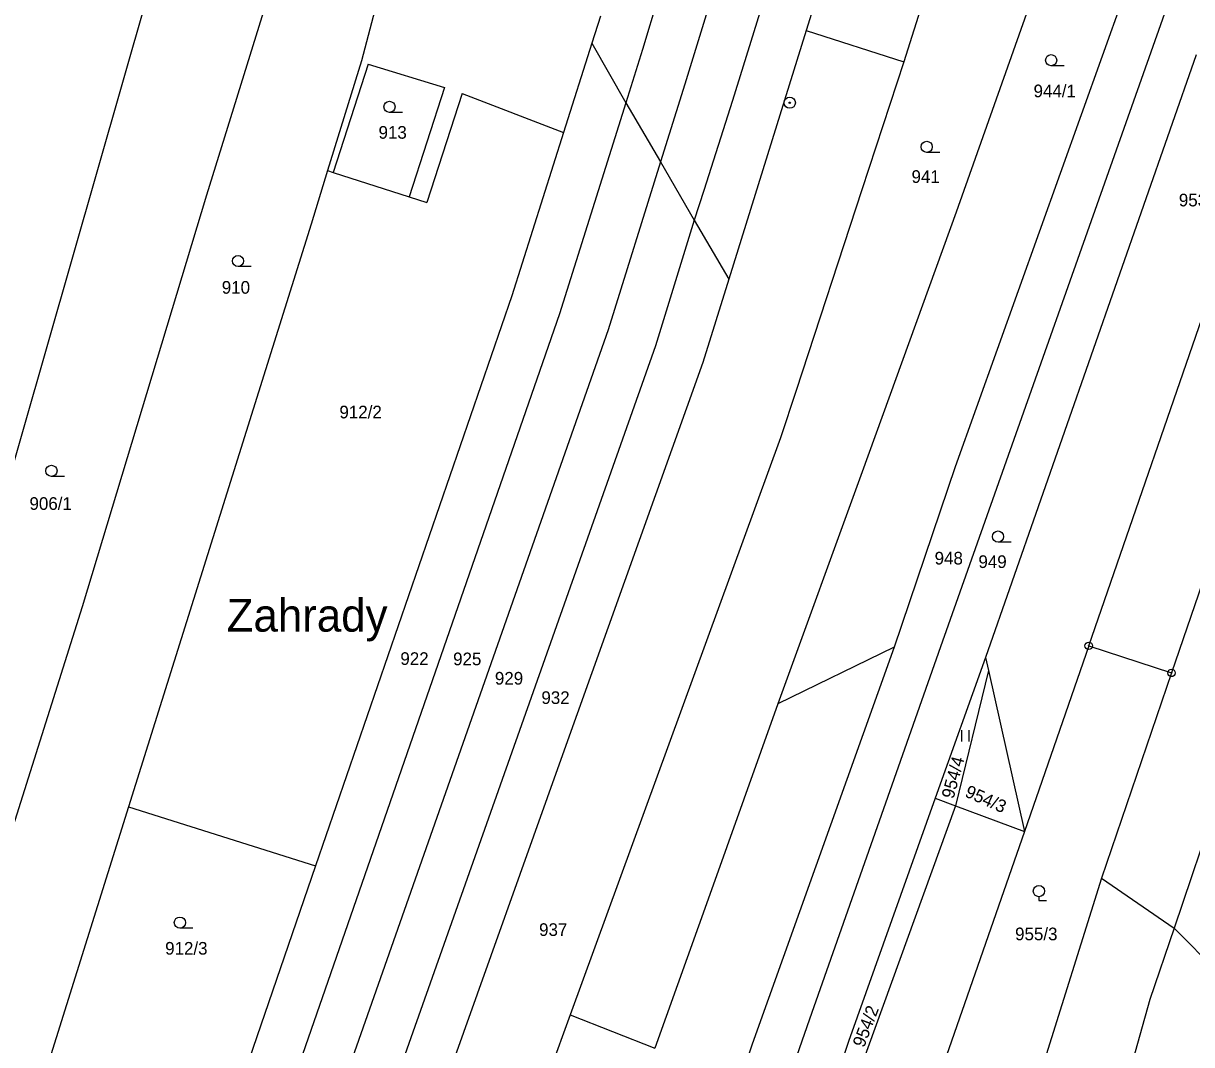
# Model space of a CAD drawing. Extents: x -593183 to -588034, y -1130415 to -1124994.
# Drawn here: x -591498.3 to -591341.4, y -1129053.4 to -1128916.3 of the extents above; entities that cross this region are included whole.
import ezdxf

# ---------------------------------------------------------------- set-up
doc = ezdxf.new("R2010")
doc.units = 0
for name, color, linetype in [('Vrstva 1', 7, 'Continuous'), ('Vrstva 15', 7, 'Continuous'), ('Vrstva 18', 7, 'Continuous'), ('Vrstva 24', 7, 'Continuous'), ('Vrstva 25', 7, 'Continuous')]:
    doc.layers.add(name, color=color, linetype=linetype)

msp = doc.modelspace()

# ---------------------------------------------------------------- linework, layer by layer
at = {"layer": 'Vrstva 1'}
for p, q in [((-591354.26, -1128888.5), (-591373.06, -1128941.67)), ((-591475.46, -1128891.06), (-591504.12, -1128991.17)), ((-591385.67, -1128893.19), (-591393.19, -1128917.3)), ((-591372.62, -1128898.03), (-591380.08, -1128921.49)), ((-591339.33, -1128898.75), (-591375.16, -1128999.99)), ((-591409.64, -1128901.35), (-591415.13, -1128919.86)), ((-591402.86, -1128903.1), (-591409.49, -1128924.51)), ((-591347.4, -1128903.87), (-591373.19, -1128975.86)), ((-591463.22, -1128905.61), (-591473.69, -1128939.41)), ((-591396.41, -1128905.12), (-591403.07, -1128926.71)), ((-591449.72, -1128909.27), (-591452.86, -1128921.36)), ((-591355.26, -1128999.87), (-591324.51, -1128910.84)), ((-591313.09, -1128912.48), (-591344.14, -1129003.51)), ((-591420.79, -1128915.38), (-591421.94, -1128918.99)), ((-591393.19, -1128917.3), (-591403.55, -1128950.65)), ((-591393.19, -1128917.3), (-591380.08, -1128921.49)), ((-591421.94, -1128918.99), (-591425.74, -1128930.99)), ((-591421.94, -1128918.99), (-591417.38, -1128927)), ((-591415.13, -1128919.86), (-591417.38, -1128927)), ((-591452.86, -1128921.36), (-591457.42, -1128936.09)), ((-591340.85, -1128920.55), (-591369.1, -1129001.43)), ((-591451.99, -1128921.8), (-591456.65, -1128936.34)), ((-591451.99, -1128921.8), (-591441.72, -1128924.93)), ((-591380.08, -1128921.49), (-591385.69, -1128938.68)), ((-591409.49, -1128924.51), (-591412.75, -1128934.94)), ((-591441.72, -1128924.93), (-591446.46, -1128939.61)), ((-591439.36, -1128925.74), (-591444.08, -1128940.37)), ((-591439.36, -1128925.74), (-591425.74, -1128930.99)), ((-591417.38, -1128927), (-591426.29, -1128955.33)), ((-591417.38, -1128927), (-591412.75, -1128934.94)), ((-591403.07, -1128926.71), (-591406.92, -1128938.75)), ((-591425.74, -1128930.99), (-591432.7, -1128952.91)), ((-591412.75, -1128934.94), (-591419.75, -1128957.47)), ((-591412.75, -1128934.94), (-591408.2, -1128942.74)), ((-591457.42, -1128936.09), (-591459.64, -1128943.27)), ((-591457.42, -1128936.09), (-591456.65, -1128936.34)), ((-591456.65, -1128936.34), (-591446.46, -1128939.61)), ((-591385.69, -1128938.68), (-591394.53, -1128965.59)), ((-591473.69, -1128939.41), (-591490.35, -1128994.63)), ((-591446.46, -1128939.61), (-591444.08, -1128940.37)), ((-591406.92, -1128938.75), (-591408.2, -1128942.74)), ((-591373.06, -1128941.67), (-591385.68, -1128976.53)), ((-591459.64, -1128943.27), (-591484.16, -1129021.5)), ((-591408.2, -1128942.74), (-591413.4, -1128959.6)), ((-591408.2, -1128942.74), (-591403.55, -1128950.65)), ((-591403.55, -1128950.65), (-591407.04, -1128961.87)), ((-591432.7, -1128952.91), (-591459.03, -1129029.38)), ((-591426.29, -1128955.33), (-591466.83, -1129072.14)), ((-591419.75, -1128957.47), (-591460.61, -1129073.72)), ((-591413.4, -1128959.6), (-591454.3, -1129075.24)), ((-591407.04, -1128961.87), (-591426.12, -1129015.15)), ((-591394.53, -1128965.59), (-591396.63, -1128971.97)), ((-591396.63, -1128971.97), (-591424.87, -1129049.39)), ((-591373.19, -1128975.86), (-591381.38, -1129000.06)), ((-591385.68, -1128976.53), (-591396.97, -1129007.68)), ((-591490.35, -1128994.63), (-591503.66, -1129036.74)), ((-591330.63, -1128998.65), (-591343.79, -1129037.78)), ((-591381.38, -1129000.06), (-591400.43, -1129053.32)), ((-591381.38, -1129000.06), (-591396.97, -1129007.68)), ((-591375.16, -1128999.99), (-591392.75, -1129050)), ((-591355.26, -1128999.87), (-591363.86, -1129024.78)), ((-591355.26, -1128999.87), (-591344.14, -1129003.51)), ((-591369.1, -1129001.43), (-591375.85, -1129020.32)), ((-591369.1, -1129001.43), (-591368.7, -1129003.19)), ((-591368.7, -1129003.19), (-591373.14, -1129021.33)), ((-591368.7, -1129003.19), (-591363.86, -1129024.78)), ((-591344.14, -1129003.51), (-591353.54, -1129031.06)), ((-591396.97, -1129007.68), (-591406.1, -1129033.24)), ((-591426.12, -1129015.15), (-591448.03, -1129076.62)), ((-591484.16, -1129021.5), (-591496.28, -1129060.24)), ((-591484.16, -1129021.5), (-591459.03, -1129029.38)), ((-591373.14, -1129021.33), (-591391.98, -1129073.25)), ((-591375.85, -1129020.32), (-591387.51, -1129052.98)), ((-591375.85, -1129020.32), (-591373.14, -1129021.33)), ((-591373.14, -1129021.33), (-591363.86, -1129024.78)), ((-591363.86, -1129024.78), (-591386.01, -1129088.36)), ((-591459.03, -1129029.38), (-591473.19, -1129070.51)), ((-591353.54, -1129031.06), (-591378.05, -1129109.01)), ((-591353.54, -1129031.06), (-591343.79, -1129037.78)), ((-591406.1, -1129033.24), (-591413.51, -1129053.85)), ((-591343.79, -1129037.78), (-591347.05, -1129047.35)), ((-591343.79, -1129037.78), (-591334.86, -1129046.79)), ((-591347.05, -1129047.35), (-591364.34, -1129108.68)), ((-591424.87, -1129049.39), (-591435.84, -1129079.45)), ((-591424.87, -1129049.39), (-591413.51, -1129053.85)), ((-591392.75, -1129050), (-591406.58, -1129089.9)), ((-591387.51, -1129052.98), (-591405.61, -1129107.39)), ((-591400.43, -1129053.32), (-591412.24, -1129088.09))]:
    msp.add_line(p, q, dxfattribs=at)
at = {"layer": 'Vrstva 24'}
for centre, radius in [((-591395.38, -1128926.99), 0.75), ((-591395.38, -1128926.99), 0.0903), ((-591355.26, -1128999.87), 0.5), ((-591355.26, -1128999.87), 0.0327), ((-591344.14, -1129003.51), 0.5), ((-591344.14, -1129003.51), 0.0327)]:
    msp.add_circle(centre, radius, dxfattribs=at)
at = {"layer": 'Vrstva 25'}
for p, q in [((-591358.55, -1128922.03), (-591360.3, -1128922.03)), ((-591447.36, -1128928.29), (-591449.11, -1128928.29)), ((-591375.25, -1128933.66), (-591377, -1128933.66)), ((-591467.69, -1128948.98), (-591469.44, -1128948.98)), ((-591492.73, -1128977.14), (-591494.48, -1128977.14)), ((-591365.68, -1128985.96), (-591367.43, -1128985.96)), ((-591372.32, -1129011.2), (-591372.32, -1129012.7)), ((-591371.3, -1129012.7), (-591371.3, -1129011.2)), ((-591361.95, -1129033.54), (-591361.95, -1129034.04)), ((-591361.95, -1129034.04), (-591360.93, -1129034.04)), ((-591475.49, -1129037.77), (-591477.24, -1129037.77))]:
    msp.add_line(p, q, dxfattribs=at)
for centre in [(-591360.3, -1128921.28), (-591449.11, -1128927.54), (-591377, -1128932.91), (-591469.44, -1128948.23), (-591494.48, -1128976.39), (-591367.43, -1128985.21), (-591361.95, -1129032.79), (-591477.24, -1129037.02)]:
    msp.add_circle(centre, 0.75, dxfattribs=at)

# ---------------------------------------------------------------- texts
at = {"layer": 'Vrstva 15'}
msp.add_text('Zahrady', height=4.4, dxfattribs=at).set_placement((-591470.96, -1128997.97))
at = {"layer": 'Vrstva 18'}
for s, p in [('944/1', (-591362.66, -1128926.26)), ('913', (-591450.58, -1128931.82)), ('941', (-591379.04, -1128937.75)), ('953', (-591343.16, -1128940.9)), ('910', (-591471.62, -1128952.62)), ('912/2', (-591455.83, -1128969.35)), ('906/1', (-591497.43, -1128981.63)), ('948', (-591375.94, -1128988.96)), ('949', (-591370.06, -1128989.43)), ('922', (-591447.65, -1129002.44)), ('925', (-591440.57, -1129002.48)), ('929', (-591434.96, -1129005.08)), ('932', (-591428.72, -1129007.68)), ('937', (-591429.03, -1129038.81)), ('955/3', (-591365.14, -1129039.39)), ('912/3', (-591479.22, -1129041.32))]:
    msp.add_text(s, height=1.7, dxfattribs=at).set_placement(p)
for s, rotation, p in [('954/4', 74.7979, (-591373.41, -1129020.5)), ('954/3', 336.0375, (-591372, -1129020.05)), ('954/2', 69.0294, (-591385.42, -1129053.88))]:
    msp.add_text(s, height=1.7, rotation=rotation, dxfattribs=at).set_placement(p)

doc.saveas('drawing.dxf')
